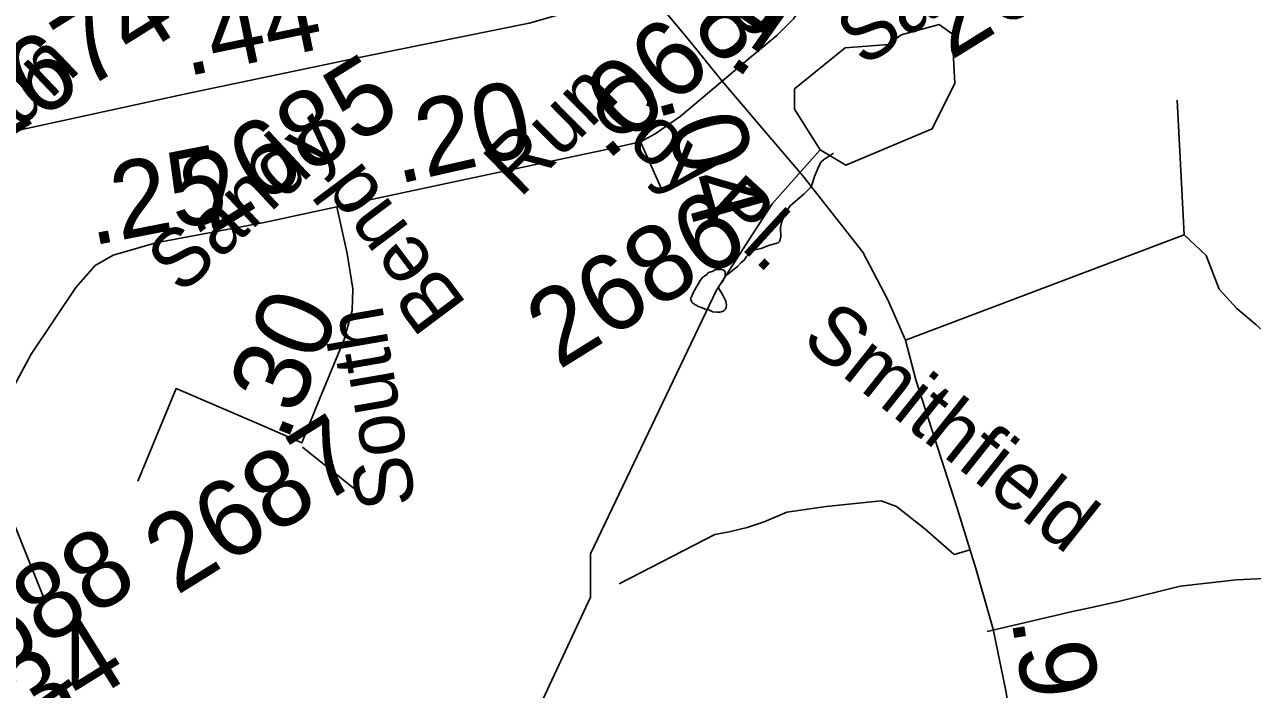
# Model space of a CAD drawing. Extents: x 2001466 to 31450019, y -30647475 to 847247.
# Drawn here: x 2160385 to 2164395, y 729877 to 732049 of the extents above; entities that cross this region are included whole.
import ezdxf

# ---------------------------------------------------------------- set-up
doc = ezdxf.new("R2010")
doc.units = 0
for name, color, linetype in [('Exist Hydrographic Misc Water Feature', 7, 'Continuous'), ('Exist Road Non-System Type 51', 7, 'Continuous'), ('Exist Road Secondary Mileage Hundredths English Label', 7, 'Continuous'), ('Exist Road Secondary Type 51 Attributed', 7, 'Continuous'), ('Exist Road Secondary Type 51 Label', 7, 'Continuous'), ('Exist Road Secondary Type 51 Number Label', 7, 'Continuous')]:
    doc.layers.add(name, color=color, linetype=linetype)

msp = doc.modelspace()

# ---------------------------------------------------------------- linework, layer by layer
at = {"layer": 'Exist Hydrographic Misc Water Feature'}
for points in [[(2162983.1, 731640.2), (2163067.2, 731589.3), (2163349.1, 731708.2), (2163423.1, 731857.5), (2163414.1, 732018.5), (2163372.1, 732048.9), (2163247.2, 732015.3), (2163206.2, 731983.3), (2163065.1, 731973.1), (2162899.2, 731838.7), (2162899.2, 731773.1), (2162983.1, 731640.2)], [(2161753.2, 729582.2), (2161862.1, 729616.1), (2162077.2, 729844.6), (2162233.2, 730179.3), (2162233.2, 730320.4), (2162644.1, 731181.3), (2162826.2, 731463), (2162983.1, 731640.2)], [(2163026.6, 731629.2), (2162994.4, 731606.9), (2162984.9, 731599), (2162974.9, 731579), (2162965, 731552.9), (2162957.2, 731528.9), (2162951.3, 731516.9), (2162929.4, 731494.7), (2162885.9, 731458.2), (2162871.5, 731438.5), (2162857.6, 731406.1), (2162853.9, 731386.4), (2162854.1, 731354.3), (2162850.4, 731340.2), (2162846.3, 731336), (2162814.5, 731327.8), (2162790.1, 731317.7), (2162774.3, 731314.1), (2162764.1, 731312), (2162754.7, 731303.6), (2162742.6, 731291.7), (2162734.6, 731279.5), (2162724.7, 731271.7), (2162712.8, 731259.3), (2162703.2, 731251.4), (2162685.1, 731235.5), (2162673.3, 731228.3)], [(2162673.3, 731228.3), (2162672.6, 731237.3), (2162673, 731241.4), (2162668.7, 731247.3), (2162661.2, 731249.3), (2162652.9, 731249.3), (2162642.9, 731249.2), (2162630.8, 731242.8), (2162618.9, 731239), (2162613, 731233), (2162605.2, 731226.9), (2162599.2, 731222.9), (2162591.2, 731212.8), (2162585.1, 731200.7), (2162578.9, 731192.7), (2162567.2, 731170.9), (2162563.5, 731160.6), (2162561.1, 731156.5), (2162559.7, 731152.6), (2162561.5, 731148.7), (2162563.5, 731142.7), (2162567.4, 731138.8), (2162573.6, 731134.7), (2162587.5, 731126.9), (2162595.3, 731124.9), (2162607.4, 731119), (2162619.5, 731117.2), (2162627.7, 731113.1)], [(2162627.7, 731113.1), (2162631.6, 731110.9), (2162645.4, 731109.2), (2162655.6, 731109.3), (2162663.6, 731111.4), (2162669.4, 731115.4), (2162673.9, 731119.1), (2162675.7, 731125.3), (2162677.6, 731131.6), (2162675.3, 731145.3), (2162663.6, 731167.3), (2162655.2, 731181.1), (2162652.9, 731185.2), (2162650.9, 731191.1), (2162653.4, 731195.2), (2162655.2, 731199), (2162658.9, 731203.3), (2162663, 731207.2), (2162669.4, 731219.2), (2162673.3, 731228.3)]]:
    msp.add_lwpolyline(points, dxfattribs=at)
at = {"layer": 'Exist Road Non-System Type 51'}
for p, q in [((2163261.6, 731018.7), (2164171.9, 731362)), ((2161292.4, 730669.2), (2161463.8, 730531.3)), ((2163473.3, 730333.4), (2163420.8, 730318.7))]:
    msp.add_line(p, q, dxfattribs=at)
for points in [[(2164171.9, 731362), (2164149.1, 731802.5)], [(2164171.9, 731362), (2164243.7, 731294.7), (2164286.3, 731184.7), (2164344.2, 731121.5), (2164405.7, 731069.4), (2164445.7, 731033.8), (2164487.1, 730994.7), (2164564.7, 730951.4)], [(2163420.8, 730318.7), (2163324.3, 730401.5), (2163232.4, 730475.1), (2163181.8, 730493.4), (2163002.6, 730475.1), (2162873.9, 730456.7)], [(2162873.9, 730456.7), (2162800.4, 730424.5), (2162745.2, 730406.1), (2162685.5, 730392.3), (2162639.5, 730383.1), (2162327, 730222.1)], [(2163961.6, 730165.6), (2164158.9, 730215), (2164342.8, 730235.2), (2164432.5, 730239.4)], [(2163528.8, 730066.9), (2163806.9, 730132), (2163878.6, 730147.7), (2163961.6, 730165.6)]]:
    msp.add_lwpolyline(points, dxfattribs=at)
at = {"layer": 'Exist Road Secondary Type 51 Attributed'}
for points in [[(2162663, 731864.5), (2162747.3, 731934.6), (2162841.5, 732013.2), (2162895.9, 732067.6), (2162960.7, 732160.8), (2163027.2, 732248.8), (2163123.5, 732327.3)], [(2162374.2, 732215.3), (2162298.9, 732153.5), (2162201.6, 732101.1), (2162033.1, 732053), (2161488.5, 731943), (2160911.9, 731822.6), (2160285.6, 731686.5), (2160162.7, 731658.2)], [(2162374.2, 732215.3), (2162451.7, 732121), (2162547.4, 732006.9), (2162663, 731864.5)], [(2162396.7, 731665.5), (2162443.8, 731691.7), (2162525.4, 731748.3), (2162663, 731864.5)], [(2162663, 731864.5), (2162775.5, 731732.6), (2162926.2, 731554.5), (2163121.9, 731305.3), (2163203.5, 731150.4), (2163261.6, 731018.7), (2163295.6, 730888.6), (2163430.6, 730469.7), (2163491.3, 730272.9), (2163547.8, 730073.9), (2163589.6, 729872.9), (2163643, 729567.1), (2163689, 729200.6), (2163767.5, 728566), (2163792.6, 728339.9), (2163815.6, 728241.4), (2163855.4, 728092.7), (2163900.4, 727952.4), (2163965.3, 727688.6), (2164023.9, 727435.1), (2164081.4, 727229.9)], [(2161404.8, 731454), (2161879.8, 731554.5), (2162264.9, 731636.2), (2162396.7, 731665.5)], [(2162396.7, 731665.5), (2162467.9, 731505.3)], [(2160351.1, 730868.7), (2160406.5, 730972.3), (2160552, 731190.1), (2160615.8, 731262.4), (2160673.9, 731295.9), (2160814.1, 731335.7), (2161167.8, 731402.7), (2161404.8, 731454)], [(2161404.8, 731454), (2161438.2, 731301.1), (2161457.1, 731186), (2161455, 731114.7), (2161428.3, 731020.5), (2161347.7, 730825.7), (2161290.7, 730683.3), (2161166.7, 730737.8), (2160880, 730860.3), (2160754.4, 730557.7)]]:
    msp.add_lwpolyline(points, dxfattribs=at)
at = {"layer": 'Exist Road Secondary Type 51 Number Label'}
msp.add_line((2160151.5, 730912.5), (2160453.5, 730162.3), dxfattribs=at)

# ---------------------------------------------------------------- texts
at = {"layer": 'Exist Road Secondary Mileage Hundredths English Label'}
for s, rotation, p in [('.12', 54.737, (2162713.5, 731861.3)), ('.08', 307.9022, (2162385.1, 732269.2)), ('.44', 11.6924, (2160913.6, 731879.1)), ('.06', 40.2807, (2162284.4, 731600.1)), ('.20', 12.7188, (2161603.6, 731527.3)), ('.04', 285.6758, (2162454.9, 731811.1)), ('.25', 11.0566, (2160603.8, 731326.1)), ('.30', 67.8896, (2161240.5, 730681.5)), ('.92', 279.33, (2163606.7, 730107.3))]:
    msp.add_text(s, height=250, rotation=rotation, dxfattribs=at).set_placement(p)
at = {"layer": 'Exist Road Secondary Type 51 Label'}
for s, rotation, p in [('Amberstone Dr.', 303.1549, (2164315.5, 732880.1)), ('Sandy', 34.9318, (2163125.3, 731906.8)), ('Run', 43.6104, (2160234.7, 731578.7)), ('Run', 44.6368, (2162001.7, 731479.2)), ('Coy Pl.', 317.5938, (2162211.3, 731783.7)), ('Sandy', 42.9747, (2160897.6, 731163.3)), ('Bend', 126.8647, (2161832.7, 731134.5)), ('South', 99.8076, (2161664.6, 730484.4)), ('Smithfield', 321.5116, (2162916.5, 731009.9)), ('Knottshill', 305.526, (2160362.1, 729818.5))]:
    msp.add_text(s, height=190, rotation=rotation, dxfattribs=at).set_placement(p)
at = {"layer": 'Exist Road Secondary Type 51 Number Label'}
for s, p in [('2685', (2163409.3, 731930.4)), ('2674', (2160265.6, 731636.1)), ('2685', (2160994.8, 731360.2)), ('2686', (2162129.4, 730919.5)), ('2687', (2160881.4, 730182.9)), ('2688', (2160134, 729819.5)), ('4334', (2160102.1, 729525.5))]:
    msp.add_text(s, height=250, rotation=31.918, dxfattribs=at).set_placement(p)

doc.saveas('drawing.dxf')
